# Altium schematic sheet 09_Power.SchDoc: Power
size A4; Date: 9/24/2014; Author: P.A.; CompanyName: STMicroelectronics; Organization: Microcontrollers Division; Address1: 12, Rue Jules HOROWITZ; Address2: 38019 Grenoble; Address3: FRANCE; DocumentNumber: 12; Revision: E-01; SheetNumber: 12; SheetTotal: 12; Project: STM32F413H-DISCO
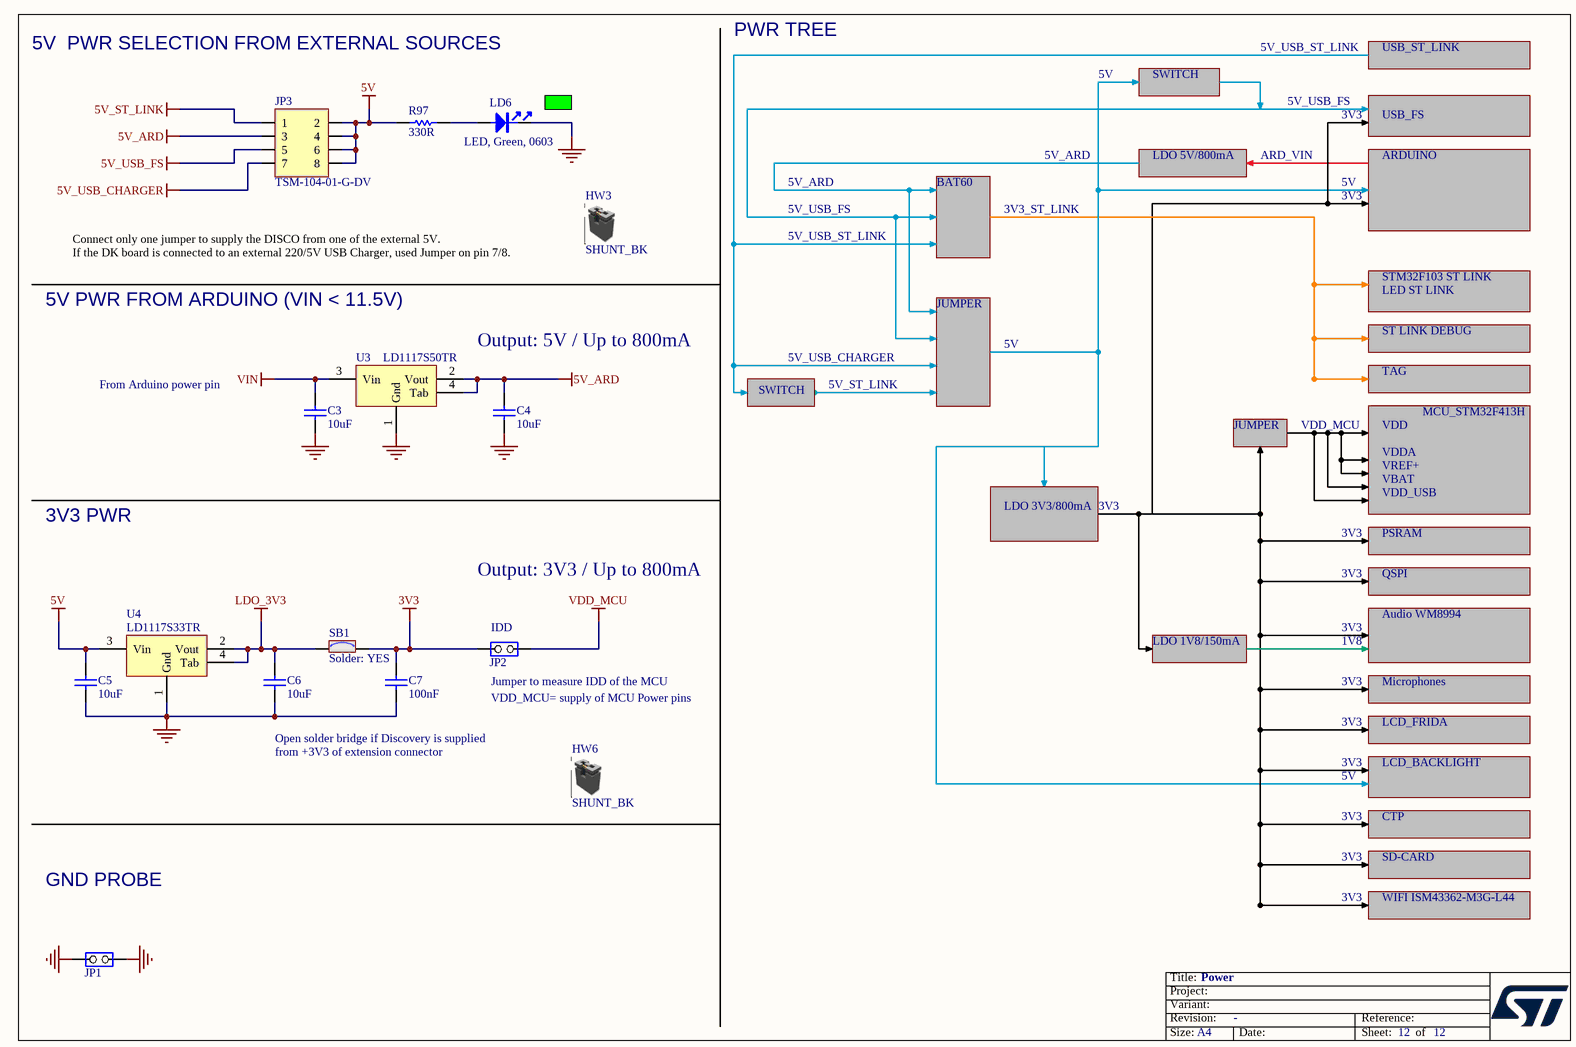
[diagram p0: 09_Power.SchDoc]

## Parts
C3  10uF  [C0805]
C4  10uF  [C0805]
C5  10uF  [C0805]
C6  10uF  [C0805]
C7  100nF  [C0402]
HW3  SHUNT_BK  (mechanical)
HW6  SHUNT_BK  (mechanical)
JP1  Jumper_2.54mm  [CON_SAMTEC_TSW-102-07-G-S]  (value not drawn)
JP2  Jumper_2.54mm  [CON_SAMTEC_TSW-102-07-G-S]  (value not drawn)
JP3  TSM-104-01-G-DV  [CON_SAMTEC_TSM-104-01-X-DV]
LD6  LED, Green, 0603  [LED_0603_GREEN]
R97  330R  [R0402]
SB1  Solder: YES  [SOLDER-BRIDGE_R0603-0R]  (hidden comment: SB_ON)
U3  LD1117S50TR  [REG_SOT223-TAB]
U4  LD1117S33TR  [REG_SOT223-TAB]

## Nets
3V3: C7.2 JP2.1(COMMON) SB1.2
5V: C5.2 JP3.2 JP3.4 JP3.6 JP3.8 R97.1 U4.3(Vin)
5V_ARD: C4.2 JP3.3 U3.2(Vout) U3.4(Tab)
5V_ST_LINK: JP3.1
5V_USB_CHARGER: JP3.7
5V_USB_FS: JP3.5
GND: C3.1 C4.1 C5.1 C6.1 C7.1 JP1.1(COMMON) JP1.2(NO) LD6.2 U3.1(Gnd) U4.1(Gnd)
LDO_3V3: C6.2 SB1.1 U4.2(Vout) U4.4(Tab)
VDD_MCU: JP2.2(NO)
VIN: C3.2 U3.3(Vin)
NetLD6_1: LD6.1 R97.2

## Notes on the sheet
- 5V  PWR SELECTION FROM EXTERNAL SOURCES
- PWR TREE
- 5V_USB_ST_LINK
- USB_ST_LINK
- 5V
- SWITCH
- 5V_USB_FS
- 3V3
- USB_FS
- 5V_ARD
- BAT60
- LDO 5V/800mA
- ARD_VIN
- ARDUINO
- Connect only one jumper to supply the DISCO from one of the external 5V.
  If the DK board is connected to an external 220/5V USB Charger, used Jumper on pin 7/8.
- 3V3_ST_LINK
- 5V PWR FROM ARDUINO (VIN < 11.5V)
- JUMPER
- STM32F103 ST LINK
- LED ST LINK
- From Arduino power pin
- Output: 5V / Up to 800mA
- 5V_USB_CHARGER
- 5V_ST_LINK
- ST LINK DEBUG
- TAG
- VDD_MCU
- VDD
- VDDA
- MCU_STM32F413H
- 3V3 PWR
- LDO 3V3/800mA
- VREF+
- VBAT
- VDD_USB
- Output: 3V3 / Up to 800mA
- PSRAM
- QSPI
- (near JP2) IDD
- LDO 1V8/150mA
- 1V8
- Audio WM8994
- (near JP2) Jumper to measure IDD of the MCU
- VDD_MCU= supply of MCU Power pins
- Microphones
- LCD_FRIDA
- Open solder bridge if Discovery is supplied
  from +3V3 of extension connector
- LCD_BACKLIGHT
- CTP
- SD-CARD
- GND PROBE
- WIFI ISM43362-M3G-L44

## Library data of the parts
C3-C6 = Cap_10uF_X5R_10%_0805: Capacitor,10uF,25V,X5R,10%,0805,YAGEO; Manuf_Part_1: CC0805KRX5R8BB106; Fitted: YES; Ordered_By: Subcon
C7 = Cap_100nF_X7R_10%_0402: Capacitor,100nF,16V,X7R,10%,0402,YAGEO; Manuf_Part_1: CC0402KRX7R7BB104; Fitted: YES; Ordered_By: Subcon
HW3 HW6 = Shunt 2.54mm: SHUNT 2.54mm BLACK; Manuf_1: SAMTEC; Manuf_Part_1: SNT-100-BK-G; Fitted: YES; Ordered_By: Subcon
JP1 JP2 = TSW-102-07-x-S: Connector jumper 1 position; Manuf_1: SAMTEC; Manuf_Part_2: 4711955140470; Manuf_2: KONTEC; Manuf_Part_1: TSW-102-07-G-S; Fitted: YES; Ordered_By: Subcon
JP3 = Header_4X2_SMD: Header, 4-Pins, Double row Vertical, SMD, 2.54; Manuf_1: SAMTEC; Fitted: YES; Ordered_By: Subcon
LD6 = LED_green: Manuf_1: everlight; Manuf_Part_1: 19-213SYGC/S530-E2/TR8; ECCN_US/EU: EAR99/NEC; Fitted: YES; Ordered_By: Subcon
R97 = Res_330_1%_0402: Resistor,330R,0402,1%,YAGEO; Manuf_Part_1: RC0402FR-07330RL; Fitted: YES; Ordered_By: Subcon
SB1 = SB_ON: Solder Bridge ON; Ordered_by: Subcon
U3 = LD1117S50TR: IC REG LDO 5V 0.8A SOT223; Manuf_1: STM; ECCN_US/EU: EAR99/NEC; Ref St: 9176133; Fitted: YES
U4 = LD1117S33TR: LOW DROP FIXED AND ADJUSTABLE POSITIVE VOLTAGE REGULATORS (3.3 Volts); Manuf_1: STM; ECCN_US/EU: EAR99/NEC; Fitted: YES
